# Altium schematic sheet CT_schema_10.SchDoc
size 147 x 119 mm
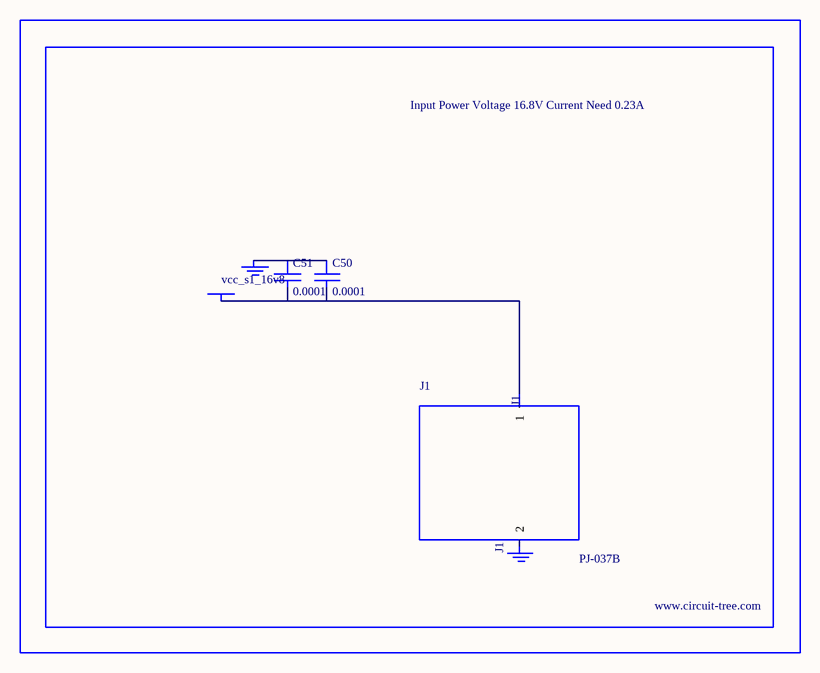
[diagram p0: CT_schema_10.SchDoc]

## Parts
BORDER9  (no value)
C50  0.0001  [EXV-9H]
C51  0.0001  [EXV-9H]
GND_INSTANCE_9_0  (no value)
GND_INSTANCE_9_1  (no value)
J1  PJ-037B  [PJ-037B_PACKAGE]
POWER_INSTANCE_9_0  vcc_s1_16v8

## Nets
NetC50_1: C50.1 C51.1 GND_INSTANCE_9_0.0(GND)
NetC50_2: C50.2 C51.2 J1.1 POWER_INSTANCE_9_0.0(PWR)

Not connected (* = marked no-connect by the designer): GND_INSTANCE_9_1 0(GND); J1 2

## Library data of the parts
BORDER9 = BORDER_PAGE9
C50 C51 = EDK107M035A9HAA
GND_INSTANCE_9_0 GND_INSTANCE_9_1 = GND
POWER_INSTANCE_9_0 = PWR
